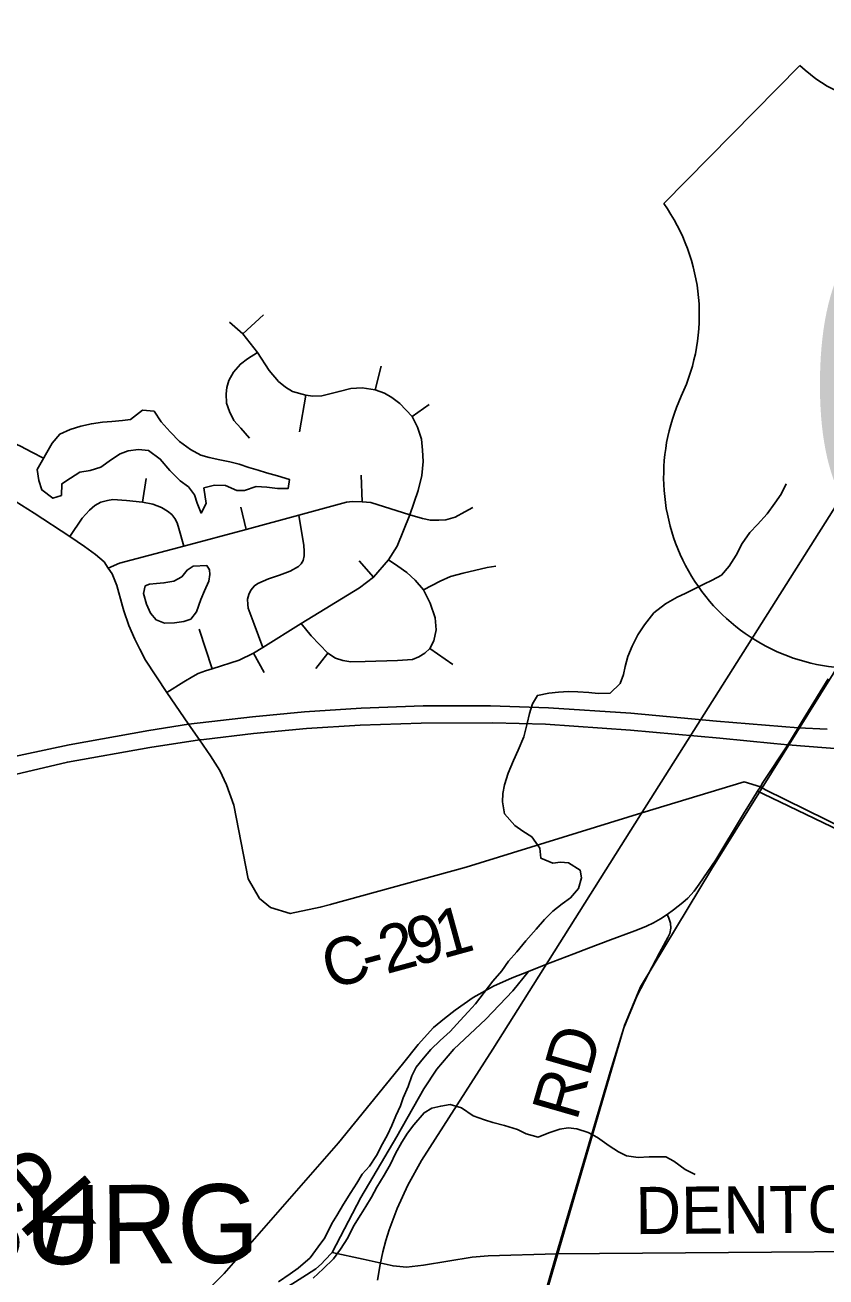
# Model space of a CAD drawing. Extents: x 114604 to 551442, y 316898 to 567001.
# Drawn here: x 161654 to 166736, y 333446 to 341392 of the extents above; entities that cross this region are included whole.
import ezdxf

# ---------------------------------------------------------------- set-up
doc = ezdxf.new("R2010")
doc.units = 0
for name, color, linetype in [('_CIVIL_CONSTRUCTION', 7, 'Continuous'), ('GE_P_Alignment_1000_Bearings', 7, 'Continuous'), ('GE_P_Alignment_1000_Cardinal_Points', 7, 'Continuous'), ('GE_P_Alignment_1000_Stations', 7, 'Continuous'), ('GE_P_Alignment_500_Bearings', 7, 'Continuous'), ('GE_P_Alignment_500_Cardinal_Points', 7, 'Continuous'), ('GE_P_Alignment_500_Stations', 7, 'Continuous'), ('MT_X_Edge_Line', 7, 'Continuous'), ('PM_P_Cells', 7, 'Continuous'), ('PM_P_CL_Double_Solid', 7, 'Continuous'), ('PM_P_Crosswalk', 7, 'Continuous'), ('RD_P_GR_Rt', 7, 'Continuous'), ('SH_Named_Boundary', 7, 'Continuous')]:
    doc.layers.add(name, color=color, linetype=linetype)

msp = doc.modelspace()

# ---------------------------------------------------------------- linework, layer by layer
at = {"layer": '_CIVIL_CONSTRUCTION'}
for p, q in [((166591.9, 336983.9), (166749.9, 337243.3)), ((166271.4, 336480.4), (166302.6, 336529.9)), ((166302.6, 336529.9), (166320.1, 336557.9))]:
    msp.add_line(p, q, dxfattribs=at)
for points in [[(166320.1, 336557.9), (166336.5, 336584), (166495, 336824.7), (166560.3, 336932), (166591.9, 336983.9)], [(165729, 335746), (165769.9, 335775.8), (165827.5, 335822), (165859.7, 335851.1), (165900.9, 335895.3), (165931.7, 335939.4), (166037.7, 336094.2), (166212.2, 336386.4), (166271.4, 336480.4)], [(165229.1, 335532.8), (165368.3, 335586.1), (165505.7, 335636.5), (165539.7, 335648.5), (165598.6, 335672.6), (165641.3, 335693.8), (165686.3, 335718.4), (165729, 335746)], [(164849.3, 335385.8), (164958.7, 335429.4), (165136.3, 335497.4), (165229.1, 335532.8)], [(162183.7, 332722.8), (162917.7, 333468.9), (163643.8, 334296.6), (164049.9, 334796.5), (164149, 334922.5), (164246.7, 335028.9), (164316.2, 335086.4), (164383.3, 335140.6), (164498.2, 335221.1), (164626.2, 335292), (164745.8, 335345.9), (164849.3, 335385.8)]]:
    msp.add_lwpolyline(points, dxfattribs=at)
at = {"layer": 'GE_P_Alignment_1000_Bearings'}
for points in [[(196041.6, 380963.5), (194033.4, 377563.3), (193868.1, 377325.2), (192058.1, 375431.3), (190340.5, 374234.8), (188290.1, 370932.4), (187383.2, 369296.1), (186211.4, 367713.7), (185191.3, 366327.4), (183802.2, 363991.4), (182496.1, 361739.6), (179755.4, 357652.8), (178697.7, 356015.2), (176027.5, 351942.2), (171808.5, 345313.1), (170010.5, 342458.8), (166009.2, 336033.6), (165560.1, 335287.7), (165457.7, 335042), (165304.5, 334515.6), (164243.2, 330883.3)], [(163891.3, 333426.4), (163907.1, 333525.5), (163925.4, 333605.3), (163944.4, 333678), (163965.3, 333745.1), (164015, 333881.6), (164083.6, 334029.3), (164170.9, 334185.3), (164621.9, 334892.6), (165400.1, 336128.7), (165560.3, 336379.1), (167341.8, 339200)]]:
    msp.add_lwpolyline(points, dxfattribs=at)
at = {"layer": 'GE_P_Alignment_1000_Cardinal_Points'}
for p, q in [((163167.3, 339553), (163035.6, 339432)), ((163874.9, 339076.1), (163913.3, 339226.9)), ((163394.8, 338811), (163436.2, 339042.5)), ((164110.8, 338907.6), (164217.8, 338983.6)), ((162398.6, 338364.9), (162422.7, 338513.6)), ((163794, 338366), (163787.4, 338534.3)), ((163057.2, 338189.5), (163023.7, 338331.3)), ((163774.8, 337992.5), (163866.2, 337886.9)), ((162758.5, 337558), (162841.8, 337305.7)), ((163104.6, 337404.7), (163172.1, 337282.6)), ((163499.9, 337308.3), (163575.7, 337405.9)), ((164369, 337333.7), (164222.3, 337436.1))]:
    msp.add_line(p, q, dxfattribs=at)
for points in [[(163874.9, 339076.1), (163792.4, 339089.8), (163722.5, 339085.7), (163647.4, 339067.3), (163588.4, 339052.5), (163538.3, 339039.6), (163481, 339037.4), (163436.2, 339042.5), (163351.8, 339066.9), (163306.8, 339093.5), (163263.5, 339129), (163203.9, 339200.3), (163129.6, 339314.4), (163035.6, 339432), (162950.8, 339506.6)], [(163078, 338771.1), (163023.8, 338833.4), (162978.6, 338883.3), (162951.3, 338940.4), (162933.1, 338992.3), (162930.9, 339051.4), (162934.1, 339090.8), (162946.4, 339135.7), (162976.4, 339189.7), (163020.9, 339240.2), (163065.4, 339274.5), (163129.6, 339314.4)], [(162553.8, 337156.3), (162661, 337223), (162718.2, 337256.7), (162753.5, 337276.1), (162798.7, 337292.7), (162841.8, 337305.7), (163012.1, 337361.5), (163104.6, 337404.7), (163163.9, 337441.2), (163405.8, 337594.6), (163776, 337821.1), (163866.2, 337886.9), (163960.4, 337998.1), (164015, 338085), (164095.6, 338283.9), (164148.2, 338438.4), (164172.7, 338533.5), (164181, 338621.4), (164176.9, 338694.8), (164169.2, 338762.8), (164145.4, 338839.7), (164110.8, 338907.6), (164031.4, 338991.2), (163981, 339028.5), (163936, 339055), (163874.9, 339076.1)], [(161938.4, 338146.5), (162017.7, 338263.3), (162062.3, 338313.5), (162096.8, 338343.3), (162134.8, 338364.6), (162177.8, 338375.5), (162211.8, 338380.6), (162297.1, 338375.5), (162398.6, 338364.9), (162464.4, 338350.8), (162519.8, 338329.2), (162557.2, 338307.6), (162585, 338285.1), (162603.8, 338260.9), (162619.5, 338231.8), (162631.1, 338196.1), (162661.1, 338084.4)], [(162182.6, 337945.9), (162254.5, 337977.6), (162661.1, 338084.4), (163057.2, 338189.5), (163391.6, 338281.7), (163694.2, 338363.2), (163733.1, 338367.3), (163794, 338366), (163847.8, 338361), (164095.6, 338283.9)], [(163391.6, 338281.7), (163424.1, 338089.2), (163425.1, 338053.1), (163426, 338024), (163419.2, 337994.2), (163405.9, 337972.2), (163389.7, 337955.8), (163336, 337927), (163268.9, 337901.1), (163199.7, 337877.9), (163131.2, 337848.4), (163109.3, 337833.3), (163086.1, 337806.2), (163073.6, 337777.8), (163066, 337747.3), (163067.7, 337714), (163070.7, 337690.7), (163107.5, 337588.9), (163163.9, 337441.2)], [(164095.6, 338283.9), (164176.4, 338259.4), (164226.7, 338249), (164280.4, 338249.4), (164325.2, 338251.5), (164384.2, 338268.1), (164444.9, 338302.6), (164496.6, 338329.8)], [(163405.8, 337594.6), (163470.8, 337515.7), (163575.7, 337405.9), (163624.1, 337373.7), (163671.7, 337358.5), (163720.6, 337351), (163812.7, 337351.7), (164018.1, 337358.8), (164113.7, 337365.9), (164153.3, 337381.8), (164191.4, 337404.7), (164222.3, 337436.1), (164248.9, 337484.4), (164264, 337552.6), (164257.7, 337629), (164225.9, 337722.3), (164182.8, 337807), (164129.9, 337869), (164077.1, 337918.2), (164018.8, 337957.4), (163960.4, 337998.1)], [(164182.8, 337807), (164288.7, 337863.1), (164355, 337891.9), (164434.2, 337913.7), (164587, 337948.8), (164642.2, 337957.7)], [(162183.7, 332722.8), (162346.1, 332782.6), (162551, 332905.7), (162919.7, 333136.9), (163369.8, 333415.6), (163441.1, 333459.8), (163499.9, 333498.2), (163534.8, 333529.9), (163556.8, 333553.9), (163602.1, 333602.1), (163785, 333950.5), (164013.3, 334337), (164185.5, 334639.5), (164267.6, 334765.7), (164375.7, 334891.8), (164577.9, 335082), (164750, 335262.1), (164849.3, 335385.8)], [(163602.1, 333602.1), (163799.4, 333559.2), (163989.6, 333516.3), (164073.9, 333509.3), (164183.3, 333520.9), (164491.4, 333571.8), (164592.6, 333581.4), (165027.1, 333593)], [(165027.1, 333593), (168298.4, 333619.2), (168386.5, 333609.1), (168410.5, 333597), (168432.5, 333558.9), (168432.5, 333498.7), (168422.5, 333440.7), (168414.5, 333402.6), (168414.1, 333371.8)]]:
    msp.add_lwpolyline(points, dxfattribs=at)
at = {"layer": 'GE_P_Alignment_1000_Stations'}
for p, q in [((166591.9, 336983.9), (166749.9, 337243.3)), ((166271.4, 336480.4), (166302.6, 336529.9)), ((166302.6, 336529.9), (166320.1, 336557.9))]:
    msp.add_line(p, q, dxfattribs=at)
for points in [[(166320.1, 336557.9), (166336.5, 336584), (166495, 336824.7), (166560.3, 336932), (166591.9, 336983.9)], [(165729, 335746), (165769.9, 335775.8), (165827.5, 335822), (165859.7, 335851.1), (165900.9, 335895.3), (165931.7, 335939.4), (166037.7, 336094.2), (166212.2, 336386.4), (166271.4, 336480.4)], [(165229.1, 335532.8), (165368.3, 335586.1), (165505.7, 335636.5), (165539.7, 335648.5), (165598.6, 335672.6), (165641.3, 335693.8), (165686.3, 335718.4), (165729, 335746)], [(164849.3, 335385.8), (164958.7, 335429.4), (165136.3, 335497.4), (165229.1, 335532.8)], [(162183.7, 332722.8), (162917.7, 333468.9), (163643.8, 334296.6), (164049.9, 334796.5), (164149, 334922.5), (164246.7, 335028.9), (164316.2, 335086.4), (164383.3, 335140.6), (164498.2, 335221.1), (164626.2, 335292), (164745.8, 335345.9), (164849.3, 335385.8)]]:
    msp.add_lwpolyline(points, dxfattribs=at)
at = {"layer": 'GE_P_Alignment_500_Bearings'}
for points in [[(162273.2, 337704.3), (162236, 337834.6), (162206.3, 337908.2), (162182.6, 337945.9), (162156.2, 337984.2), (162102.3, 338031.7), (162032.2, 338082.3), (161938.4, 338146.5), (161712.7, 338294.6), (161511.5, 338420.7), (161362.6, 338482.3), (161276.7, 338502)], [(163598.5, 335812.1), (163593.4, 335810.7), (163527.2, 335792.4), (163337.1, 335752.6), (163211, 335790.8), (163142.9, 335848.9), (163070.9, 335973.3), (162978.8, 336440.6), (162931.5, 336568.9), (162889.2, 336661.2), (162830.6, 336753.4), (162761.8, 336854.8), (162692.1, 336955.8), (162553.8, 337156.3), (162419.1, 337361.5), (162381.8, 337429.9), (162350.2, 337494.9), (162312.7, 337580.3), (162281.8, 337674.2), (162273.2, 337704.3)], [(166320.1, 336557.9), (166217.2, 336589.6), (165568.4, 336391.9), (164454, 336048), (163598.5, 335812.1)], [(165680.7, 335502.7), (165732.9, 335601.8), (165746.1, 335625.6), (165751.6, 335659.3), (165749.1, 335691.1), (165739.6, 335722.9), (165729, 335746)], [(164247.2, 330883.8), (165027.1, 333593), (165367.1, 334747.4), (165452.9, 335027.9), (165539.2, 335233.5), (165680.7, 335502.7)]]:
    msp.add_lwpolyline(points, dxfattribs=at)
at = {"layer": 'GE_P_Alignment_500_Cardinal_Points'}
msp.add_line((166571.4, 341135.1), (165707.5, 340258.7), dxfattribs=at)
for points in [[(166302.6, 336529.9), (166337, 336512.6), (166989, 336199.2), (167051.3, 336177), (167101.2, 336169.9), (167148.4, 336171), (167187.8, 336177.6), (167227.9, 336191.3), (167257.2, 336204.5), (167288.7, 336224.8), (167353.7, 336281.5), (167645.6, 336555.5), (167685.5, 336584.4), (167729.3, 336607.1), (167761.4, 336622.5), (167786.3, 336632.5), (167822.4, 336643.9), (167877.1, 336655.1), (167925, 336659.3), (168053.1, 336667.4), (168053.3, 336709.5)], [(166994.1, 336223.5), (166353.1, 336537.2), (166320.1, 336557.9)]]:
    msp.add_lwpolyline(points, dxfattribs=at)
for centre, radius, start, end in [((167176, 341760.9), 870.2, 225.98551, 314.83952), ((164714.6, 339552.8), 1218.3, 334.95963, 35.41344), ((166924.7, 338527), 1218.3, 155.24442, 271.05077)]:
    msp.add_arc(centre, radius, start, end, dxfattribs=at)
at = {"layer": 'GE_P_Alignment_500_Stations'}
for points in [[(161486.6, 336727.8), (161934.8, 336822.9), (162440, 336914.1), (162692.1, 336955.8), (163096.8, 337002.2), (163427.3, 337033.8), (163787.1, 337057.2), (164180.3, 337071.2), (164607, 337071.5), (164975.4, 337058.9), (165498.2, 337025.1), (166042, 336974.8), (166560.3, 336932), (166744.2, 336924)], [(162787.7, 336857.9), (163104.8, 336894.8), (163439.5, 336926.4), (163779.8, 336948.3), (164167.5, 336962.3), (164621.9, 336964.1), (164956.9, 336954), (165496.5, 336916.2), (166063.9, 336866.1), (166406.7, 336833.2)], [(159877, 336094), (159988.7, 336138.6), (160290.2, 336252.7), (160602.8, 336359.8), (161072.9, 336502.2), (161480.7, 336609.4), (161923.3, 336714), (162445.2, 336806.7), (162761.8, 336854.8), (162787.7, 336857.9)], [(166406.7, 336833.2), (166495, 336824.7), (166738.4, 336805.6), (167036.8, 336781), (167667.3, 336728.9), (168053.3, 336709.5)]]:
    msp.add_lwpolyline(points, dxfattribs=at)
at = {"layer": 'MT_X_Edge_Line'}
for points in [[(161730.4, 338570.3), (161741.8, 338502.1), (161761.4, 338441.8), (161831, 338389.1), (161885.3, 338406.6), (161887.9, 338480.8), (161942.3, 338516.4), (162002.7, 338553.9), (162066.9, 338565.4), (162135.1, 338586.9), (162203.6, 338634.4), (162258, 338670), (162308.3, 338689.6), (162374.4, 338699), (162438.5, 338692.5), (162512.1, 338637.7), (162573.6, 338565), (162639.2, 338500.3), (162690.9, 338461.8), (162728.6, 338411.4), (162746.2, 338357.1), (162771.7, 338294.8), (162804.2, 338354.6), (162789, 338454.9), (162857.3, 338472.4), (162925.4, 338469.8), (162997.2, 338437.1), (163047.3, 338438.7), (163121.6, 338464.1), (163187.7, 338459.5), (163255.7, 338450.9), (163323.8, 338450.3), (163332.3, 338508.4), (163256.4, 338531.1), (163186.4, 338549.7), (163132.5, 338566.2), (163074.6, 338584.8), (163012.6, 338605.3), (162952.7, 338619.9), (162890.7, 338632.4), (162822.7, 338647.1), (162768.7, 338661.6), (162704.9, 338698.2), (162635.3, 338748.9), (162575.7, 338809.5), (162518.1, 338874.2), (162472.6, 338940.7), (162398.5, 338947.3), (162323.9, 338887.9), (162271.8, 338882.3), (162205.7, 338876.9), (162145.5, 338871.4), (162075.3, 338862), (162009.1, 338846.5), (161940.8, 338825), (161874.5, 338795.5), (161825.9, 338737.8)], [(161825.9, 338737.8), (161730.4, 338570.3)], [(162720.8, 337958.5), (162682.5, 337932.8), (162648.1, 337889), (162597.8, 337863.3), (162535.6, 337851.8), (162487.5, 337848.3), (162443.4, 337842.6), (162417.3, 337832.8), (162404.9, 337784.8), (162424.3, 337716.5), (162449.9, 337660.2), (162485.6, 337617.8), (162539.5, 337595.3), (162601.6, 337598.7), (162661.8, 337606.2), (162706, 337621.9), (162742.4, 337667.7), (162769.1, 337745.6), (162793.6, 337801.5), (162820.2, 337863.4), (162826.5, 337905.5), (162824.8, 337935.5), (162807, 337961.7)], [(162807, 337961.7), (162720.8, 337958.5)]]:
    msp.add_lwpolyline(points, dxfattribs=at)
at = {"layer": 'PM_P_Cells'}
for points in [[(161183.1, 338879.7), (161244.3, 338883.2), (161296.1, 338858.7), (161352.1, 338840.1), (161423.9, 338809.5), (161479.8, 338782.9), (161539.7, 338758.4), (161625.5, 338719.5), (161697.3, 338680.8), (161772, 338643.3)], [(166484.9, 338481.2), (166452.3, 338415.3), (166411.7, 338357.5), (166363.1, 338289.8), (166302.4, 338222.2), (166253.9, 338170.5), (166205.3, 338100.8), (166166.6, 338026.9), (166121.9, 337957.2), (166073.4, 337901.5), (166015, 337867.9), (165960.8, 337844.3), (165894.4, 337808.8), (165842.1, 337785.2), (165791.8, 337761.6), (165717.3, 337718.1), (165644.8, 337660.7), (165584, 337585), (165543.4, 337521.2), (165506.8, 337449.4), (165478.2, 337383.5), (165461.7, 337321.5), (165451.2, 337269.5), (165430.7, 337213.5), (165368.1, 337151.9), (165290, 337150.6), (165231.9, 337155.1), (165161.9, 337159.7), (165101.8, 337162.2), (165039.7, 337158.8), (164977.5, 337151.3), (164905.3, 337137.9), (164874.8, 337084), (164854.2, 337022.1), (164839.7, 336958.1), (164818.9, 336874.1), (164784.2, 336790.2), (164753.6, 336724.3), (164718.9, 336644.4), (164696.2, 336570.4), (164685.7, 336514.4), (164683.3, 336462.3), (164696.7, 336386), (164762.2, 336311.3), (164814, 336276.8), (164869.7, 336240.2), (164921.2, 336167.6), (164926.7, 336105.4), (165002.5, 336072.7), (165052.7, 336078.3), (165102.7, 336075.8), (165176.4, 336029.1), (165186, 335978.9), (165165.4, 335912.9), (165114.9, 335853.2), (165062.5, 335815.6), (165004, 335768), (164949.5, 335714.3), (164896.9, 335654.6), (164832.1, 335579), (164775.5, 335509.4), (164722.9, 335449.7), (164680.3, 335389.9), (164621.7, 335324.3), (164512.3, 335180.9), (164465.8, 335129.1), (164415.3, 335073.5), (164352.6, 335003.8), (164288, 334946.3), (164229.5, 334890.6), (164182.9, 334834.9), (164136.4, 334777.2), (164107.9, 334723.3), (164085.3, 334655.3), (164052.6, 334583.4), (164036.2, 334531.5), (164007.6, 334469.6), (163981, 334407.6), (163954.5, 334347.7), (163922, 334291.9), (163885.3, 334218), (163840.7, 334150.2), (163794.2, 334098.5), (163759.6, 334040.7), (163721.1, 333982.9), (163674.4, 333909.1), (163631.7, 333837.3), (163601.3, 333785.4), (163556.4, 333695.6), (163513.9, 333637.8), (163463.2, 333568.1), (163386.6, 333502.6), (163336.2, 333467), (163261.6, 333415.5)], [(163482.2, 333439.6), (163546.8, 333497.2), (163611.4, 333560.8), (163656, 333622.6), (163702.6, 333694.3), (163739.3, 333768.2), (163784, 333842), (163816.5, 333893.8), (163853, 333953.7), (163885.6, 334015.5), (163932.3, 334093.3), (163973, 334163.1), (164005.6, 334229), (164044.3, 334302.8), (164080.8, 334358.7), (164121.3, 334412.4), (164186, 334488.1), (164236.4, 334517.7), (164292.6, 334531.2), (164352.7, 334540.7), (164424.7, 334520.1), (164498.3, 334469.3), (164570.2, 334442.6), (164622.2, 334426.2), (164696.1, 334407.5), (164780.1, 334382.7), (164833.9, 334354.2), (164909.8, 334333.4), (164978.2, 334360.9), (165048.5, 334384.4), (165100.6, 334391.9), (165154.6, 334385.5), (165226.6, 334362.8), (165286.4, 334332.2), (165360.1, 334279.4), (165419.8, 334240.8), (165471.7, 334214.3), (165545.7, 334203.7), (165613.9, 334209.1), (165667.9, 334208.6), (165720, 334208.2), (165771.9, 334181.6), (165843.5, 334128.9), (165907.4, 334096.3)]]:
    msp.add_lwpolyline(points, dxfattribs=at)

# ---------------------------------------------------------------- texts
at = {"layer": 'GE_P_Alignment_500_Cardinal_Points'}
msp.add_text('62', height=2088.44, rotation=0.41252, dxfattribs=at).set_placement((166563.7, 338089.4))
at = {"layer": 'PM_P_CL_Double_Solid'}
for s, height, rotation, p in [('9', 300, 15.36919, (164125.1, 335416.5)), ('1', 300, 15.38107, (164303.4, 335465.5)), ('2', 300, 15.28718, (163946.4, 335367.7)), ('C', 300, 14.27166, (163583, 335273.3)), ('-', 300, 15.09451, (163826.4, 335335.3)), ('RD', 300.02, 73.85262, (165154.7, 334430.4))]:
    msp.add_text(s, height=height, rotation=rotation, dxfattribs=at).set_placement(p)
at = {"layer": 'PM_P_Crosswalk'}
msp.add_text('DENTON', height=300.02, rotation=0.41248, dxfattribs=at).set_placement((165528.5, 333717.7))
at = {"layer": 'RD_P_GR_Rt'}
msp.add_text('Creek', height=500.09, rotation=310.40292, dxfattribs=at).set_placement((160664, 334888.4))
at = {"layer": 'SH_Named_Boundary'}
msp.add_text('HARRISBURG', height=500.04, rotation=0.41234, dxfattribs=at).set_placement((158683.2, 333504.8))

doc.saveas('drawing.dxf')
